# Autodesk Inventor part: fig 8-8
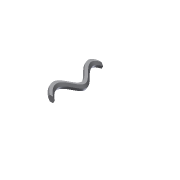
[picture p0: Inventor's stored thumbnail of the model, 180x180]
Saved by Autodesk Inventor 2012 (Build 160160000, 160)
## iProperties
Created: 2006-01
Part Number: fig 8-8
Document SubType Name: Modeling
Designer: CADCIM
Density: 1 g/cm^3
Material: Default
Author: CADCIM
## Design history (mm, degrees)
sketch "Sketch1"
  geometry: 5 further points
  constraints: 5 other
sketch "Sketch2"
  geometry: L1 (-4.728, 0)-(-2.364, 4.094); L2 (-2.364, 4.094)-(2.364, 4.094); L3 (2.364, 4.094)-(4.728, 0); L4 (4.728, 0)-(2.364, -4.094); L5 (2.364, -4.094)-(-2.364, -4.094); L6 (-2.364, -4.094)-(-4.728, 0); 1 further point
  constraints: 12 end point, 13 other
sweep "Sweep4" sketch "Sketch1", "Sketch2" dims "d3" = 0
body "Solid2"
